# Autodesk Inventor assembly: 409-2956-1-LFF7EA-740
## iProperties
Created: 2010-09
Part Number: 409-2956-1-LFF7EA-740
Document SubType Name: Weldment
Designer: S. Boerckel
Weld Material: Welded Stainless Steel, 440C
Mass: 43508.5 g
Surface Area: 16478.2 cm^2
Volume: 5479.06 cm^3
Density: 7.94087 g/cm^3
Description: DISCHARGE SPOOL
Material: WELDMENT
SMR: =<MATERIAL>
Author: S. Boerckel
Revision Number: B
